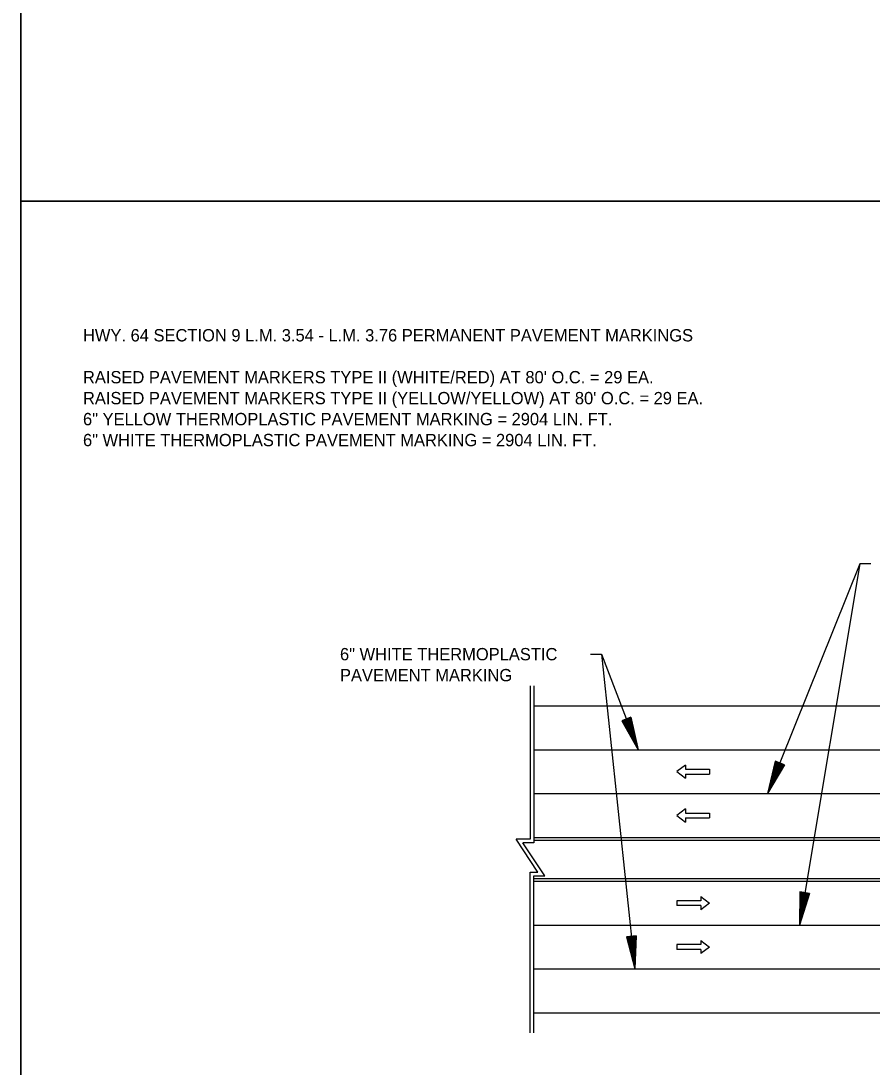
# Model space of a CAD drawing. Extents: x 1373096 to 1373266, y 381130 to 381790.
# Drawn here: x 1373096 to 1373173.6, y 381271.2 to 381366.6 of the extents above; entities that cross this region are included whole.
import ezdxf

# ---------------------------------------------------------------- set-up
doc = ezdxf.new("R2010")
doc.units = 0
for name, color, linetype in [('Default', 7, 'Continuous'), ('DSN_DRFT_Junk-No-Plot', 7, 'Continuous'), ('R_Draft', 7, 'Continuous')]:
    doc.layers.add(name, color=color, linetype=linetype)

msp = doc.modelspace()

# ---------------------------------------------------------------- linework, layer by layer
at = {"layer": 'Default'}
for p, q in [((1373172.526, 381317.08), (1373164.114, 381296.128)), ((1373172.526, 381317.08), (1373167.011, 381284.128)), ((1373173.526, 381317.08), (1373172.526, 381317.08)), ((1373147.952, 381308.848), (1373148.952, 381308.848)), ((1373148.952, 381308.848), (1373152.299, 381300.128)), ((1373148.952, 381308.848), (1373151.995, 381280.128)), ((1373142.445, 381305.965), (1373142.445, 381291.961)), ((1373142.778, 381305.965), (1373142.778, 381291.628)), ((1373151.644, 381303.09), (1373150.804, 381302.767)), ((1373150.804, 381302.767), (1373152.299, 381300.128)), ((1373150.874, 381302.794), (1373152.12, 381300.596)), ((1373150.946, 381302.822), (1373151.935, 381301.077)), ((1373151.016, 381302.849), (1373151.756, 381301.544)), ((1373151.087, 381302.876), (1373151.574, 381302.018)), ((1373151.158, 381302.903), (1373151.394, 381302.486)), ((1373151.29, 381302.954), (1373151.394, 381302.486)), ((1373151.36, 381302.981), (1373151.574, 381302.018)), ((1373151.433, 381303.009), (1373151.756, 381301.544)), ((1373151.503, 381303.036), (1373151.935, 381301.077)), ((1373151.574, 381303.063), (1373152.12, 381300.596)), ((1373151.644, 381303.09), (1373152.299, 381300.128)), ((1373164.814, 381299.08), (1373164.114, 381296.128)), ((1373164.884, 381299.052), (1373164.301, 381296.593)), ((1373164.955, 381299.023), (1373164.493, 381297.072)), ((1373165.025, 381298.995), (1373164.679, 381297.535)), ((1373165.65, 381298.744), (1373164.814, 381299.08)), ((1373165.096, 381298.967), (1373164.869, 381298.007)), ((1373165.167, 381298.938), (1373165.055, 381298.472)), ((1373156.607, 381298.728), (1373155.829, 381298.128)), ((1373155.829, 381298.128), (1373156.607, 381297.528)), ((1373156.607, 381298.728), (1373156.607, 381298.353)), ((1373156.607, 381298.353), (1373158.814, 381298.353)), ((1373158.814, 381298.353), (1373158.814, 381297.903)), ((1373165.65, 381298.744), (1373164.114, 381296.128)), ((1373165.58, 381298.772), (1373164.301, 381296.593)), ((1373165.509, 381298.801), (1373164.493, 381297.072)), ((1373165.439, 381298.829), (1373164.679, 381297.535)), ((1373165.367, 381298.858), (1373164.869, 381298.007)), ((1373165.297, 381298.886), (1373165.055, 381298.472)), ((1373156.607, 381297.903), (1373158.814, 381297.903)), ((1373156.607, 381297.903), (1373156.607, 381297.528)), ((1373156.607, 381294.728), (1373155.829, 381294.128)), ((1373156.607, 381294.728), (1373156.607, 381294.353)), ((1373156.607, 381294.353), (1373158.814, 381294.353)), ((1373158.814, 381294.353), (1373158.814, 381293.903)), ((1373155.829, 381294.128), (1373156.607, 381293.528)), ((1373156.607, 381293.903), (1373158.814, 381293.903)), ((1373156.607, 381293.903), (1373156.607, 381293.528)), ((1373143.155, 381288.961), (1373141.155, 381291.961)), ((1373142.445, 381291.961), (1373141.155, 381291.961)), ((1373142.778, 381291.628), (1373141.778, 381291.628)), ((1373143.778, 381288.628), (1373141.778, 381291.628)), ((1373142.445, 381288.961), (1373143.155, 381288.961)), ((1373142.445, 381274.291), (1373142.445, 381288.961)), ((1373142.778, 381274.291), (1373142.778, 381288.628)), ((1373142.778, 381288.628), (1373143.778, 381288.628)), ((1373158.035, 381286.728), (1373158.035, 381286.353)), ((1373158.035, 381286.728), (1373158.814, 381286.128)), ((1373167.062, 381287.161), (1373167.011, 381284.128)), ((1373167.95, 381287.012), (1373167.011, 381284.128)), ((1373167.95, 381287.012), (1373167.062, 381287.161)), ((1373167.136, 381287.149), (1373167.093, 381284.622)), ((1373167.876, 381287.025), (1373167.093, 381284.622)), ((1373167.211, 381287.136), (1373167.179, 381285.131)), ((1373167.8, 381287.037), (1373167.179, 381285.131)), ((1373167.285, 381287.124), (1373167.261, 381285.624)), ((1373167.726, 381287.05), (1373167.261, 381285.624)), ((1373167.361, 381287.111), (1373167.345, 381286.125)), ((1373167.649, 381287.063), (1373167.345, 381286.125)), ((1373167.436, 381287.098), (1373167.428, 381286.619)), ((1373167.575, 381287.075), (1373167.428, 381286.619)), ((1373158.035, 381286.353), (1373155.829, 381286.353)), ((1373155.829, 381286.353), (1373155.829, 381285.903)), ((1373158.035, 381285.903), (1373155.829, 381285.903)), ((1373158.814, 381286.128), (1373158.035, 381285.528)), ((1373158.035, 381285.903), (1373158.035, 381285.528)), ((1373152.126, 381283.159), (1373151.231, 381283.064)), ((1373151.231, 381283.064), (1373151.995, 381280.128)), ((1373151.306, 381283.072), (1373151.942, 381280.626)), ((1373151.382, 381283.08), (1373151.888, 381281.139)), ((1373151.456, 381283.088), (1373151.835, 381281.636)), ((1373151.532, 381283.096), (1373151.781, 381282.142)), ((1373151.609, 381283.104), (1373151.729, 381282.64)), ((1373151.749, 381283.119), (1373151.729, 381282.64)), ((1373151.823, 381283.127), (1373151.781, 381282.142)), ((1373151.901, 381283.135), (1373151.835, 381281.636)), ((1373151.975, 381283.143), (1373151.888, 381281.139)), ((1373152.052, 381283.151), (1373151.942, 381280.626)), ((1373152.126, 381283.159), (1373151.995, 381280.128)), ((1373158.035, 381282.728), (1373158.035, 381282.353)), ((1373158.035, 381282.728), (1373158.814, 381282.128)), ((1373158.035, 381282.353), (1373155.829, 381282.353)), ((1373155.829, 381282.353), (1373155.829, 381281.903)), ((1373158.035, 381281.903), (1373155.829, 381281.903)), ((1373158.814, 381282.128), (1373158.035, 381281.528)), ((1373158.035, 381281.903), (1373158.035, 381281.528))]:
    msp.add_line(p, q, dxfattribs=at)
for points in [[(1373095.974, 381460.174), (1373095.974, 381350.174), (1373265.974, 381350.174), (1373265.974, 381460.174)], [(1373095.974, 381350.174), (1373095.974, 381240.174), (1373265.974, 381240.174), (1373265.974, 381350.174)]]:
    msp.add_lwpolyline(points, close=True, dxfattribs=at)
at = {"layer": 'DSN_DRFT_Junk-No-Plot'}
for points in [[(1373095.974, 381460.174), (1373265.974, 381460.174), (1373265.974, 381350.174), (1373095.974, 381350.174)], [(1373095.974, 381460.174), (1373095.974, 381350.174), (1373265.974, 381350.174), (1373265.974, 381460.174)], [(1373095.974, 381350.174), (1373265.974, 381350.174), (1373265.974, 381240.174), (1373095.974, 381240.174)], [(1373095.974, 381350.174), (1373095.974, 381240.174), (1373265.974, 381240.174), (1373265.974, 381350.174)]]:
    msp.add_lwpolyline(points, close=True, dxfattribs=at)
at = {"layer": 'R_Draft'}
for p, q in [((1373142.778, 381304.128), (1373219.169, 381304.128)), ((1373142.778, 381300.128), (1373219.169, 381300.128)), ((1373142.778, 381296.128), (1373219.169, 381296.128)), ((1373142.778, 381292.128), (1373219.169, 381292.128)), ((1373142.778, 381291.878), (1373219.169, 381291.878)), ((1373142.778, 381288.378), (1373219.169, 381288.378)), ((1373142.778, 381288.128), (1373219.169, 381288.128)), ((1373142.778, 381284.128), (1373219.169, 381284.128)), ((1373142.778, 381280.128), (1373219.169, 381280.128)), ((1373142.778, 381276.128), (1373219.169, 381276.128))]:
    msp.add_line(p, q, dxfattribs=at)

# ---------------------------------------------------------------- texts
at = {"layer": 'Default'}
for s, p in [('HWY. 64 SECTION 9 L.M. 3.54 - L.M. 3.76 PERMANENT PAVEMENT MARKINGS', (1373101.637, 381337.385)), ("RAISED PAVEMENT MARKERS TYPE II (WHITE/RED) AT 80' O.C. = 29 EA.", (1373101.637, 381333.561)), ("RAISED PAVEMENT MARKERS TYPE II (YELLOW/YELLOW) AT 80' O.C. = 29 EA.", (1373101.637, 381331.649)), ('6" YELLOW THERMOPLASTIC PAVEMENT MARKING = 2904 LIN. FT.', (1373101.637, 381329.736)), ('6" WHITE THERMOPLASTIC PAVEMENT MARKING = 2904 LIN. FT.', (1373101.637, 381327.824)), ('6" WHITE THERMOPLASTIC', (1373125.09, 381308.286)), ('PAVEMENT MARKING', (1373125.09, 381306.373))]:
    msp.add_text(s, height=1.125, dxfattribs=at).set_placement(p)

doc.saveas('drawing.dxf')
